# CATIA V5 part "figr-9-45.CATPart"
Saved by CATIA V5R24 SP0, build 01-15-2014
Part number: Part1
Bounding box of the stored display mesh (mm): x -159.661 to 182.627, y -78.048 to 78.048, z 0 to 72.429
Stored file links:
  D:\KAVITA\CATIA V5-6R2014 Project_ Kavita\CATIA V5-6R2014_partfiles\Partfiles\c09_catia_v5-6r2014_prt\figr-9-45.CATPart
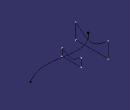
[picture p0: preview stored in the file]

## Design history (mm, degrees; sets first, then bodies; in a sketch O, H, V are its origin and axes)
Body1 (main body)
  Plane1: type Offset, RefPlane yz-plane, Offset 100
  Plane2: type Offset, RefPlane yz-plane, Offset 100, reversed
  Sketch1 on Plane1, origin (100, 0, 0), H (0, 1, 0), V (0, 0, 1)
    point P1 (0, 15.965)
    hyperbola C1
    point P2 (0, 3.0416)
    line L1 (54.8261, 44.8858) -> (54.8261, 0)
    point P5 (54.8261, 0)
    line L2 (-54.8261, 44.8858) -> (-54.8261, 0)
    point P6 (-54.8261, 0)
    line L3 (-54.8261, 0) -> (54.8261, 0)
    coincidence: P1 V, P2 V, P5 H, P6 H
    vertical: L1 V, L2 V
    horizontal: L3 H
  Sketch2 on xy-plane, origin (0, 0, 0), H (1, 0, 0), V (0, 1, 0)
    spline S1 through (-159.6608, -77.1468) (-77.8466, -31.8169) (23.6283, -41.4968) (182.6271, -11.7333)
  Sketch3 on yz-plane, origin (0, 0, 0), H (0, 1, 0), V (0, 0, 1)
    point P1 (0, 18.9787)
    hyperbola C1
    point P2 (0, 2.6681)
    line L1 (48.2237, 37.1764) -> (48.2237, 0)
    point P5 (48.2237, 0)
    line L2 (-43.6563, 34.1546) -> (-43.6563, 0)
    point P6 (-43.6563, 0)
    line L3 (-43.6563, 0) -> (48.2237, 0)
    coincidence: P1 V, P2 V, P5 H, P6 H
    vertical: L1 V, L2 V
    horizontal: L3 H
  Sketch4 on Plane2, origin (-100, 0, 0), H (0, 1, 0), V (0, 0, 1)
    point P1 (0, 140.6052)
    point P2 (0, 41.8972)
    hyperbola C1
    line L1 (78.0478, 72.4293) -> (78.0478, 0)
    point P5 (78.0478, 0)
    line L2 (-78.0478, 72.4293) -> (-78.0478, 0)
    point P6 (-78.0478, 0)
    line L3 (-78.0478, 0) -> (78.0478, 0)
    coincidence: P1 V, P2 V, P5 H, P6 H
    vertical: L1 V, L2 V
    horizontal: L3 H
  Loft1: solid, Sections (Sketch3; Sketch4), Spine Sketch2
